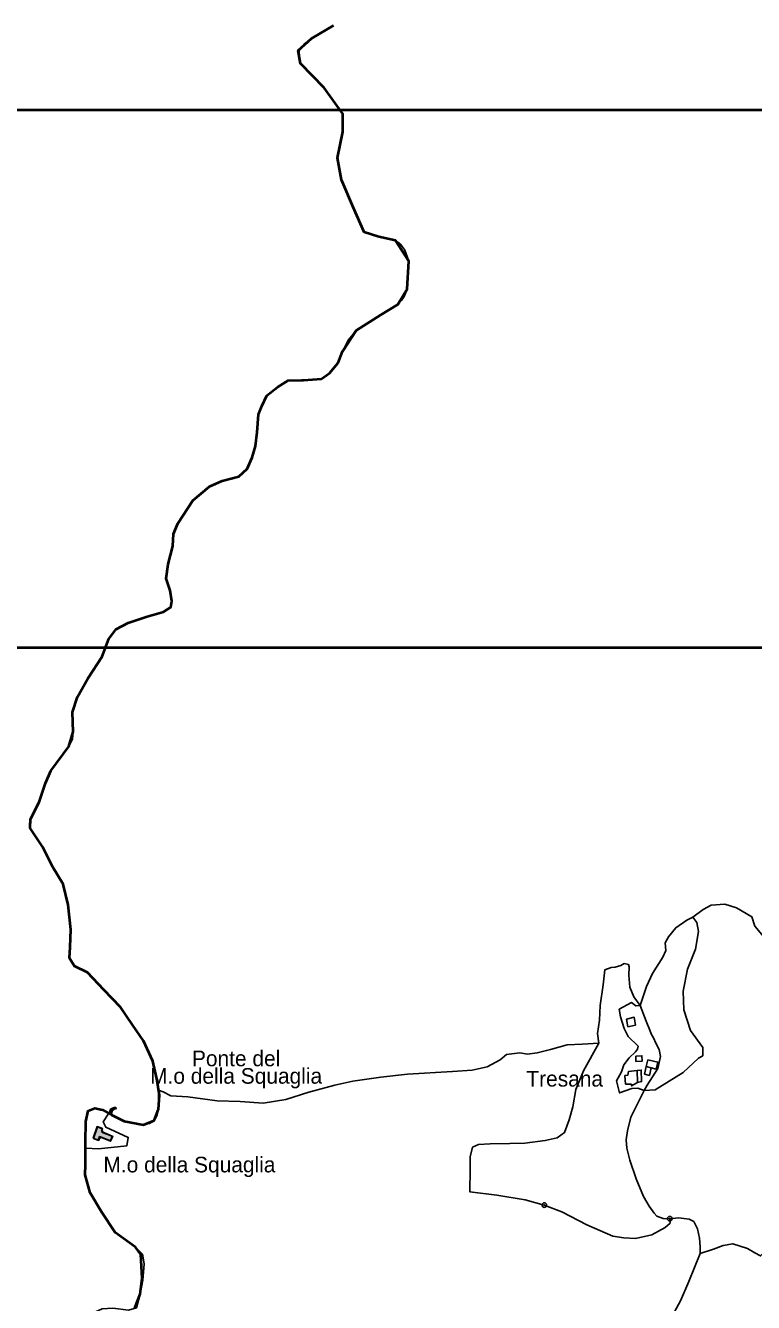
# Model space of a CAD drawing. Extents: x 645880 to 658994, y 884400 to 894744.
# Drawn here: x 651612 to 652403, y 888292 to 889680 of the extents above; entities that cross this region are included whole.
import ezdxf
from ezdxf.enums import TextEntityAlignment as Align

# ---------------------------------------------------------------- set-up
doc = ezdxf.new("R2010")
doc.units = 0
doc.header["$LTSCALE"] = 10
doc.header["$PDMODE"] = 32
doc.header["$PDSIZE"] = 5
for name, color, linetype, lineweight in [('1', 7, 'Continuous', 25), ('16', 7, 'Continuous', 25), ('18', 7, 'Continuous', 25), ('4', 7, 'Continuous', 25), ('59', 7, 'Continuous', 40), ('62', 7, 'Continuous', 35), ('63', 7, 'Continuous', 35), ('7', 7, 'Continuous', 25)]:
    doc.layers.add(name, color=color, linetype=linetype, lineweight=lineweight)
doc.layers.add('60', color=7, linetype='Continuous')

msp = doc.modelspace()

# ---------------------------------------------------------------- hatches: boundary and pattern name
at = {"layer": '4'}
msp.add_hatch(color=256, dxfattribs=at).paths.add_polyline_path([(651708.51, 888504.09), (651705.36, 888502.72), (651703.72, 888501.35), (651702.9, 888498.33), (651705.23, 888497.24), (651705.64, 888499.98), (651707.96, 888501.76), (651710.29, 888502.72)])
at = {"layer": '7'}
msp.add_hatch(color=256, dxfattribs=at).paths.add_polyline_path([(651689.79, 888482.66), (651685.54, 888469.91), (651690.9, 888467.87), (651692.93, 888471.57), (651704.02, 888466.95), (651706.6, 888472.12), (651695.15, 888476.38), (651694.96, 888480.63)])

# ---------------------------------------------------------------- linework, layer by layer
at = {"layer": '1'}
for points in [[(652277.83, 888570.19), (652277, 888567.16), (652274.69, 888564.07), (652267.99, 888557.53), (652262.29, 888550.17), (652259.54, 888542.47), (652254, 888532.81), (652257.58, 888519.57), (652270.69, 888524.37), (652277.39, 888524.49), (652284.1, 888522.19), (652287.39, 888528.07), (652299.02, 888545.95), (652301.84, 888558.92), (652300.44, 888566.8), (652296.49, 888574.17), (652294.66, 888578.75), (652291.78, 888583.62), (652290.44, 888587.57), (652286.46, 888597.44), (652280.04, 888614.51), (652275.35, 888614.19), (652270.33, 888617.76), (652257.21, 888610.37)], [(652257.21, 888610.37), (652258.51, 888602.17), (652262.57, 888589.36), (652266.89, 888580.93), (652277.83, 888570.19)], [(652276.51, 888543.8), (652267.17, 888542.64), (652266.66, 888538.96), (652263.37, 888538.3), (652263.93, 888528.85)], [(652263.93, 888528.85), (652270.43, 888528.97), (652270.58, 888527.1), (652276.92, 888530.88), (652276.51, 888543.8)]]:
    msp.add_lwpolyline(points, dxfattribs=at)
for points in [[(652264.99, 888599.84), (652273.37, 888601.73), (652274.74, 888593), (652266.53, 888591.4)], [(652275, 888559.63), (652281.84, 888559.91), (652282.08, 888554.08), (652275.25, 888553.8)], [(652288.29, 888555.55), (652286.53, 888548.07), (652291.86, 888546.81), (652297.43, 888545.5), (652299.19, 888552.99)], [(652276.51, 888543.8), (652281.13, 888544.29), (652281.44, 888531.78), (652276.92, 888530.88)], [(652284.57, 888539.79), (652286.52, 888548.07), (652291.86, 888546.81), (652289.91, 888538.53)]]:
    msp.add_lwpolyline(points, close=True, dxfattribs=at)
at = {"layer": '16'}
for points in [[(652296.49, 888574.17), (652300.44, 888566.8), (652301.84, 888558.92), (652299.02, 888545.95), (652287.39, 888528.07), (652284.1, 888522.19), (652296.14, 888522.71), (652326.61, 888541.76), (652343.36, 888557.35), (652348.05, 888559.95), (652348.05, 888569.05), (652334.65, 888587.25), (652327.28, 888609.99), (652326.61, 888630.13), (652331.3, 888654.18), (652340.01, 888675.62), (652343.36, 888695.12), (652341.35, 888704.86), (652337.33, 888710.71), (652330.63, 888707.46), (652318.58, 888699.02), (652310.54, 888689.27), (652307.19, 888682.77), (652307.86, 888674.32), (652304.51, 888667.17), (652293.13, 888649.31), (652286.77, 888635.01), (652280.07, 888614.54)], [(652280.07, 888614.54), (652272.92, 888623.99), (652268.57, 888634.38), (652267.56, 888647.38), (652267.9, 888656.48), (652267.23, 888659.08), (652262.54, 888660.05), (652258.86, 888658.1), (652252.83, 888656.15), (652248.48, 888655.83), (652241.36, 888653.22), (652239.69, 888637.1), (652236.34, 888614.36), (652235.67, 888598.44), (652233.66, 888584.14), (652235, 888573.42), (652218.27, 888543.68), (652209.9, 888523.21), (652206.55, 888504.37), (652202.53, 888490.4), (652197.51, 888476.42), (652189.47, 888470.58), (652176.41, 888467.65), (652154.65, 888464.73), (652138.24, 888464.4), (652116.81, 888464.08), (652104.08, 888463.43), (652097.72, 888460.5), (652095.04, 888450.11), (652095.04, 888436.55), (652094.54, 888412.01), (652123.91, 888408.28), (652154.67, 888403.15), (652175.65, 888397.55)], [(652257.21, 888610.37), (652270.33, 888617.76), (652275.35, 888614.19), (652280.04, 888614.51)], [(652277.83, 888570.19), (652266.89, 888580.93), (652262.57, 888589.36), (652258.51, 888602.17), (652257.21, 888610.37)], [(652280.04, 888614.51), (652286.46, 888597.44), (652290.44, 888587.57), (652291.78, 888583.62), (652294.66, 888578.75), (652296.49, 888574.17)], [(652284.1, 888522.19), (652277.39, 888524.49), (652270.69, 888524.37), (652257.58, 888519.57), (652254, 888532.81), (652259.54, 888542.47), (652262.29, 888550.17), (652267.99, 888557.53), (652274.69, 888564.07), (652277, 888567.16), (652277.83, 888570.19)], [(652175.65, 888397.55), (652194.68, 888390.33), (652221.8, 888376.1), (652250.23, 888363.97), (652262.29, 888361.96), (652274.68, 888361.31), (652292.65, 888365.37), (652307.1, 888373.3), (652312.69, 888377.96), (652312.03, 888382.78), (652305.03, 888383.03), (652298.04, 888385.64), (652294.98, 888388.88), (652289.59, 888396.43), (652283.57, 888406.83), (652275.56, 888426.16), (652268.52, 888446.3), (652265.51, 888459.3), (652264.84, 888468.4), (652266.18, 888478.15), (652269.86, 888493.09), (652284.1, 888522.19)]]:
    msp.add_lwpolyline(points, dxfattribs=at)
msp.add_point((652175.65, 888397.55), dxfattribs=at)
at = {"layer": '18'}
for points in [[(651909.07, 889652.46), (651914.94, 889660.01), (651922.67, 889665.75), (651946.51, 889679.79)], [(651910.75, 889638.49), (651909.28, 889645.32), (651909.07, 889652.46)], [(651955.03, 889512.09), (651952.68, 889522.37), (651950.77, 889536.04), (651956.73, 889564.13), (651956.73, 889583.96), (651936.29, 889612.05), (651910.75, 889638.49)], [(652028.27, 889423.69), (652023.98, 889435.72), (652019.35, 889442.01), (652013.79, 889446), (651995.91, 889450.13), (651979.73, 889455.08), (651967.8, 889482.35), (651955.03, 889512.09)], [(652016.34, 889376.6), (652020.61, 889381.38), (652023.56, 889385.78), (652026.56, 889393.12), (652028.27, 889423.69)], [(651956.27, 889325.59), (651962.75, 889338.16), (651971.17, 889348.31), (651998, 889365.25), (652016.34, 889376.6)], [(651658.71, 888896.1), (651662.71, 888904.5), (651663.39, 888912.21), (651662.54, 888933.27), (651668.07, 888950.21), (651679.15, 888970.04), (651694.9, 888993.99), (651702.14, 889013), (651710.23, 889023.74), (651723, 889030.34), (651744.01, 889037.53), (651761.47, 889042.49), (651769.56, 889047.45), (651770.84, 889054.06), (651768.71, 889065.62), (651764.45, 889078.84), (651766.58, 889094.12), (651771.69, 889113.95), (651772.54, 889127.17), (651777.22, 889138.32), (651793.4, 889163.52), (651811.71, 889178.8), (651825.34, 889185), (651843.65, 889189.54), (651852.59, 889197.8), (651858.13, 889210.2), (651861.53, 889222.59), (651863.44, 889237.61), (651864.72, 889257.02), (651874.09, 889277.67), (651885.59, 889286.76), (651897.08, 889293.78), (651933.28, 889295.85), (651942.22, 889302.05), (651951.59, 889313.2), (651956.27, 889325.59)], [(651616.63, 888807.19), (651615.74, 888812.19), (651617.06, 888817.1), (651626.43, 888835.69), (651633.24, 888856.34), (651639.2, 888869.56), (651658.71, 888896.1)], [(651664.75, 888657.48), (651661.02, 888661.96), (651659.22, 888666.16), (651660.07, 888677.9), (651660.92, 888697.31), (651657.94, 888724.16), (651652.4, 888746.47), (651641.33, 888765.06), (651630.26, 888786.54), (651616.63, 888807.19)], [(652404.5, 888700.79), (652401.33, 888711.08), (652384.72, 888720.58), (652372.06, 888724.54), (652357.02, 888723.75), (652348.32, 888719), (652337.33, 888710.71), (652330.63, 888707.46), (652318.58, 888699.02), (652310.54, 888689.27), (652307.19, 888682.77), (652307.86, 888674.32), (652304.51, 888667.17), (652293.13, 888649.31), (652286.77, 888635.01), (652280.07, 888614.54), (652272.92, 888623.99), (652268.57, 888634.38), (652267.56, 888647.38), (652267.9, 888656.48), (652267.23, 888659.08), (652262.54, 888660.05), (652258.86, 888658.1), (652252.83, 888656.15), (652248.48, 888655.83)], [(652337.33, 888710.71), (652348.32, 888719), (652357.02, 888723.75), (652372.06, 888724.54), (652384.72, 888720.58), (652401.33, 888711.08), (652404.5, 888700.79), (652413.99, 888689.7), (652424.28, 888677.03), (652437.09, 888663.22), (652451.28, 888648.63), (652464.64, 888636.65), (652474, 888628.17), (652481.58, 888625.71), (652490.48, 888628.36), (652499.75, 888634.42), (652510.16, 888640.86), (652524.17, 888639.91), (652536.65, 888637.44), (652550.68, 888636.69), (652562.76, 888642.19), (652580.19, 888650.17), (652581.69, 888641.17), (652587.19, 888635.16)], [(652269.86, 888493.09), (652284.1, 888522.19), (652296.14, 888522.71), (652326.61, 888541.76), (652343.36, 888557.35), (652348.05, 888559.95), (652348.05, 888569.05), (652334.65, 888587.25), (652327.28, 888609.99), (652326.61, 888630.13), (652331.3, 888654.18), (652340.01, 888675.62), (652343.36, 888695.12), (652341.35, 888704.86), (652337.33, 888710.71)], [(652235, 888573.42), (652216.79, 888572.4), (652200.5, 888571.78), (652182.31, 888566.76), (652167.9, 888562.99), (652157.24, 888561.74), (652149.09, 888562.99), (652134.67, 888561.11), (652127.77, 888555.47), (652113.36, 888547.94), (652097.06, 888544.17), (652075.74, 888542.92), (652026.84, 888539.78), (651998, 888536.65), (651967.29, 888532.26), (651947.85, 888527.86), (651919.64, 888520.34), (651894.57, 888512.17), (651870.12, 888508.41), (651845.04, 888510.29), (651819.97, 888510.92), (651787.88, 888515.26), (651769.7, 888516.2), (651761.08, 888520.51), (651756.22, 888522.63), (651754.17, 888534.8), (651749.91, 888554.21), (651739.69, 888576.11), (651727.77, 888593.46), (651715, 888612.87), (651678.8, 888650.46), (651664.75, 888657.48)], [(652248.48, 888655.83), (652241.36, 888653.22), (652239.69, 888637.1), (652236.34, 888614.36), (652235.67, 888598.44), (652233.66, 888584.14), (652235, 888573.42)], [(651756.22, 888522.63), (651761.08, 888520.51), (651769.7, 888516.2), (651787.88, 888515.26), (651819.97, 888510.92), (651845.04, 888510.29), (651870.12, 888508.41), (651894.57, 888512.17), (651919.64, 888520.34), (651947.85, 888527.86), (651967.29, 888532.26), (651998, 888536.65), (652026.84, 888539.78), (652075.74, 888542.92), (652097.06, 888544.17), (652113.36, 888547.94), (652127.77, 888555.47), (652134.67, 888561.11), (652149.09, 888562.99), (652157.24, 888561.74), (652167.9, 888562.99), (652182.31, 888566.76), (652200.5, 888571.78), (652216.79, 888572.4), (652235, 888573.42), (652218.27, 888543.68), (652209.9, 888523.21), (652206.55, 888504.37), (652202.53, 888490.4), (652197.51, 888476.42), (652189.47, 888470.58), (652176.41, 888467.65), (652154.65, 888464.73), (652138.24, 888464.4), (652116.81, 888464.08), (652104.08, 888463.43), (652097.72, 888460.5), (652095.04, 888450.11), (652095.04, 888436.55), (652094.54, 888412.01)], [(651751.62, 888489.56), (651754.75, 888495.59), (651756.3, 888501.75), (651756.22, 888522.63)], [(651676.83, 888459.62), (651690.83, 888458.62), (651721.82, 888462.12), (651723.32, 888471.12), (651698.83, 888482.13), (651695.83, 888488.13), (651702.15, 888497.39)], [(651702.18, 888497.42), (651718.83, 888488.73), (651739.69, 888485.02)], [(651739.69, 888485.02), (651746.36, 888486.35), (651751.62, 888489.56)], [(652312.03, 888382.78), (652305.03, 888383.03), (652298.04, 888385.64), (652294.98, 888388.88), (652289.59, 888396.43), (652283.57, 888406.83), (652275.56, 888426.16), (652268.52, 888446.3), (652265.51, 888459.3), (652264.84, 888468.4), (652266.18, 888478.15), (652269.86, 888493.09)], [(651679.17, 888183.52), (651674.63, 888197.73), (651669.19, 888209.23), (651662.85, 888224.95), (651661.94, 888240.68), (651667.38, 888257.32), (651673.26, 888269.69), (651684.33, 888280.01), (651694.98, 888284.97), (651706.48, 888285.38), (651723.65, 888283.39), (651732.07, 888285.72), (651736.28, 888300.67), (651739, 888316.08), (651740.59, 888333.89), (651738.85, 888344.08), (651731.18, 888352.01), (651709.04, 888367.7), (651694.13, 888390.42), (651681.78, 888411.08), (651676.25, 888430.49), (651676.86, 888459.65)], [(652094.54, 888412.01), (652123.91, 888408.28), (652154.67, 888403.15), (652175.65, 888397.55), (652194.68, 888390.33), (652221.8, 888376.1), (652250.23, 888363.97), (652262.29, 888361.96), (652274.68, 888361.31), (652292.65, 888365.37), (652307.1, 888373.3), (652312.69, 888377.96), (652312.03, 888382.78), (652321.63, 888383.83), (652333.06, 888382.25), (652338.41, 888379.57), (652342.37, 888371.78), (652344.37, 888361.74), (652345.04, 888352.37), (652345.04, 888345.01), (652332.93, 888314.37), (652323.7, 888293.52), (652317.21, 888281.72)], [(652404.58, 888345.67), (652396.55, 888350.36), (652380.49, 888355.47), (652370.27, 888353.7), (652359.76, 888349.69), (652345.04, 888345.01), (652345.04, 888352.37), (652344.37, 888361.74), (652342.37, 888371.78), (652338.41, 888379.57), (652333.06, 888382.25), (652321.63, 888383.83), (652312.03, 888382.78)], [(652317.21, 888281.72), (652323.7, 888293.52), (652332.93, 888314.37), (652345.04, 888345.01)], [(652345.04, 888345.01), (652359.76, 888349.69), (652370.27, 888353.7), (652380.49, 888355.47), (652396.55, 888350.36), (652404.58, 888345.67), (652410.75, 888342.29), (652420.92, 888352.57), (652424.94, 888346.07), (652442.35, 888338.92), (652491.91, 888335.67), (652507.99, 888335.67), (652521.38, 888329.18), (652530.76, 888318.13), (652544.15, 888303.18), (652552.19, 888299.93), (652575.63, 888304.48), (652597.73, 888312.93), (652623.18, 888325.93), (652637.91, 888338.92)]]:
    msp.add_lwpolyline(points, dxfattribs=at)
msp.add_point((652312.03, 888382.78), dxfattribs=at)
at = {"layer": '4'}
for points in [[(651690.83, 888458.62), (651676.83, 888459.62), (651676.95, 888473.96), (651677.07, 888488.29), (651679.62, 888499.86), (651686.33, 888502.14), (651695.38, 888501.1), (651702.15, 888497.39), (651695.83, 888488.13), (651698.83, 888482.13), (651723.32, 888471.12), (651721.82, 888462.12)], [(651708.51, 888504.09), (651705.36, 888502.72), (651703.72, 888501.35), (651702.9, 888498.33), (651705.23, 888497.24), (651705.64, 888499.98), (651707.96, 888501.76), (651710.29, 888502.72)], [(651685.13, 888470.22), (651689.37, 888482.97), (651695.23, 888480.85), (651694.25, 888477.64), (651705.76, 888472.32), (651704.02, 888467.53), (651692.15, 888472.12), (651690.38, 888467.99)]]:
    msp.add_lwpolyline(points, close=True, dxfattribs=at)
at = {"layer": '59'}
for points in [[(651864.69, 889256.99), (651868.52, 889266.08), (651874.06, 889277.64), (651885.56, 889286.73), (651897.05, 889293.75), (651913.66, 889294.17), (651933.25, 889295.82), (651942.19, 889302.02), (651951.56, 889313.17), (651956.24, 889325.56), (651971.14, 889348.28), (651997.97, 889365.22), (652016.31, 889376.57), (652026.53, 889393.09), (652028.24, 889423.66), (652013.76, 889445.97), (651995.88, 889450.1), (651979.7, 889455.05), (651967.77, 889482.32), (651955, 889512.06), (651950.74, 889536.01), (651956.7, 889564.1), (651956.7, 889583.93), (651936.26, 889612.02), (651910.72, 889638.46), (651908.16, 889652.5), (651922.64, 889665.72), (651946.48, 889679.76)], [(651659.19, 888666.13), (651660.04, 888677.87), (651660.89, 888697.28), (651657.91, 888724.13), (651652.37, 888746.44), (651641.3, 888765.03), (651630.23, 888786.51), (651616.6, 888807.16), (651617.03, 888817.07), (651626.4, 888835.66), (651633.21, 888856.31), (651639.17, 888869.53), (651658.68, 888896.07), (651663.36, 888912.18), (651662.51, 888933.24), (651668.04, 888950.18), (651679.12, 888970.01), (651694.87, 888993.96), (651702.11, 889012.97), (651710.2, 889023.71), (651722.97, 889030.31), (651743.98, 889037.5), (651761.44, 889042.46), (651769.53, 889047.42), (651770.81, 889054.03), (651768.68, 889065.59), (651764.42, 889078.81), (651766.55, 889094.09), (651771.66, 889113.92), (651772.51, 889127.14), (651777.19, 889138.29), (651793.37, 889163.49), (651811.68, 889178.77), (651825.31, 889184.97), (651843.62, 889189.51), (651852.56, 889197.77), (651858.1, 889210.17), (651861.5, 889222.56), (651863.41, 889237.58), (651864.69, 889256.99)], [(651730.29, 888285.76), (651736.25, 888300.64), (651738.38, 888317.98), (651737.1, 888344.01), (651731.15, 888351.98), (651709.01, 888367.67), (651694.1, 888390.39), (651681.75, 888411.05), (651676.22, 888430.46), (651676.64, 888441.61), (651676.64, 888465.99), (651677.07, 888488.29), (651679.62, 888499.86), (651686.86, 888502.75), (651695.38, 888501.1), (651705.17, 888495.73), (651718.8, 888488.7), (651739.66, 888484.99), (651751.59, 888489.53), (651756.27, 888501.72), (651757.12, 888516.59), (651754.14, 888534.77), (651749.88, 888554.18), (651739.66, 888576.08), (651727.74, 888593.43), (651714.97, 888612.84), (651696.66, 888631.43), (651678.77, 888650.43), (651664.72, 888657.45), (651659.19, 888666.13)]]:
    msp.add_lwpolyline(points, dxfattribs=at)
at = {"layer": '62', "lineweight": 40}
msp.add_lwpolyline([(650022.35, 889003.81), (658994.16, 889003.81), (658994.16, 894743.81), (650022.35, 894743.81)], close=True, dxfattribs=at)
msp.add_lwpolyline([(650022.35, 889003.81), (658994.16, 889003.81), (658994.16, 894743.81), (650022.35, 894743.81)], close=True, dxfattribs=at)
at = {"layer": '63', "lineweight": 40}
msp.add_lwpolyline([(656397.82, 884399.72), (650080.32, 884399.72), (650080.32, 889588.16), (656397.82, 889588.16)], close=True, dxfattribs=at)
at = {"layer": '7'}
msp.add_lwpolyline([(651689.79, 888482.66), (651685.54, 888469.91), (651690.9, 888467.87), (651692.93, 888471.57), (651704.02, 888466.95), (651706.6, 888472.12), (651695.15, 888476.38), (651694.96, 888480.63)], close=True, dxfattribs=at)

# ---------------------------------------------------------------- texts
at = {"layer": '60'}
for s, p in [('Ponte del', (651840.55, 888548.49)), ('M.o della Squaglia', (651840.55, 888529.5)), ('Tresana', (652197.83, 888526.42)), ('M.o della Squaglia', (651789.79, 888433.11))]:
    msp.add_text(s, height=17, dxfattribs=at).set_placement(p, align=Align.CENTER)

doc.saveas('drawing.dxf')
